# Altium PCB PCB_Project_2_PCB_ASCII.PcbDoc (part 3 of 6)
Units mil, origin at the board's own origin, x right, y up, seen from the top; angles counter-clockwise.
Board outline 3900 x 7800 mil, 6 copper layers (Top Layer, GND 1, Signal, Power, GND 2, Bottom Layer), stack 62.1 mil thick; 636 components, 334 nets, 1830 pads, 1401 vias.
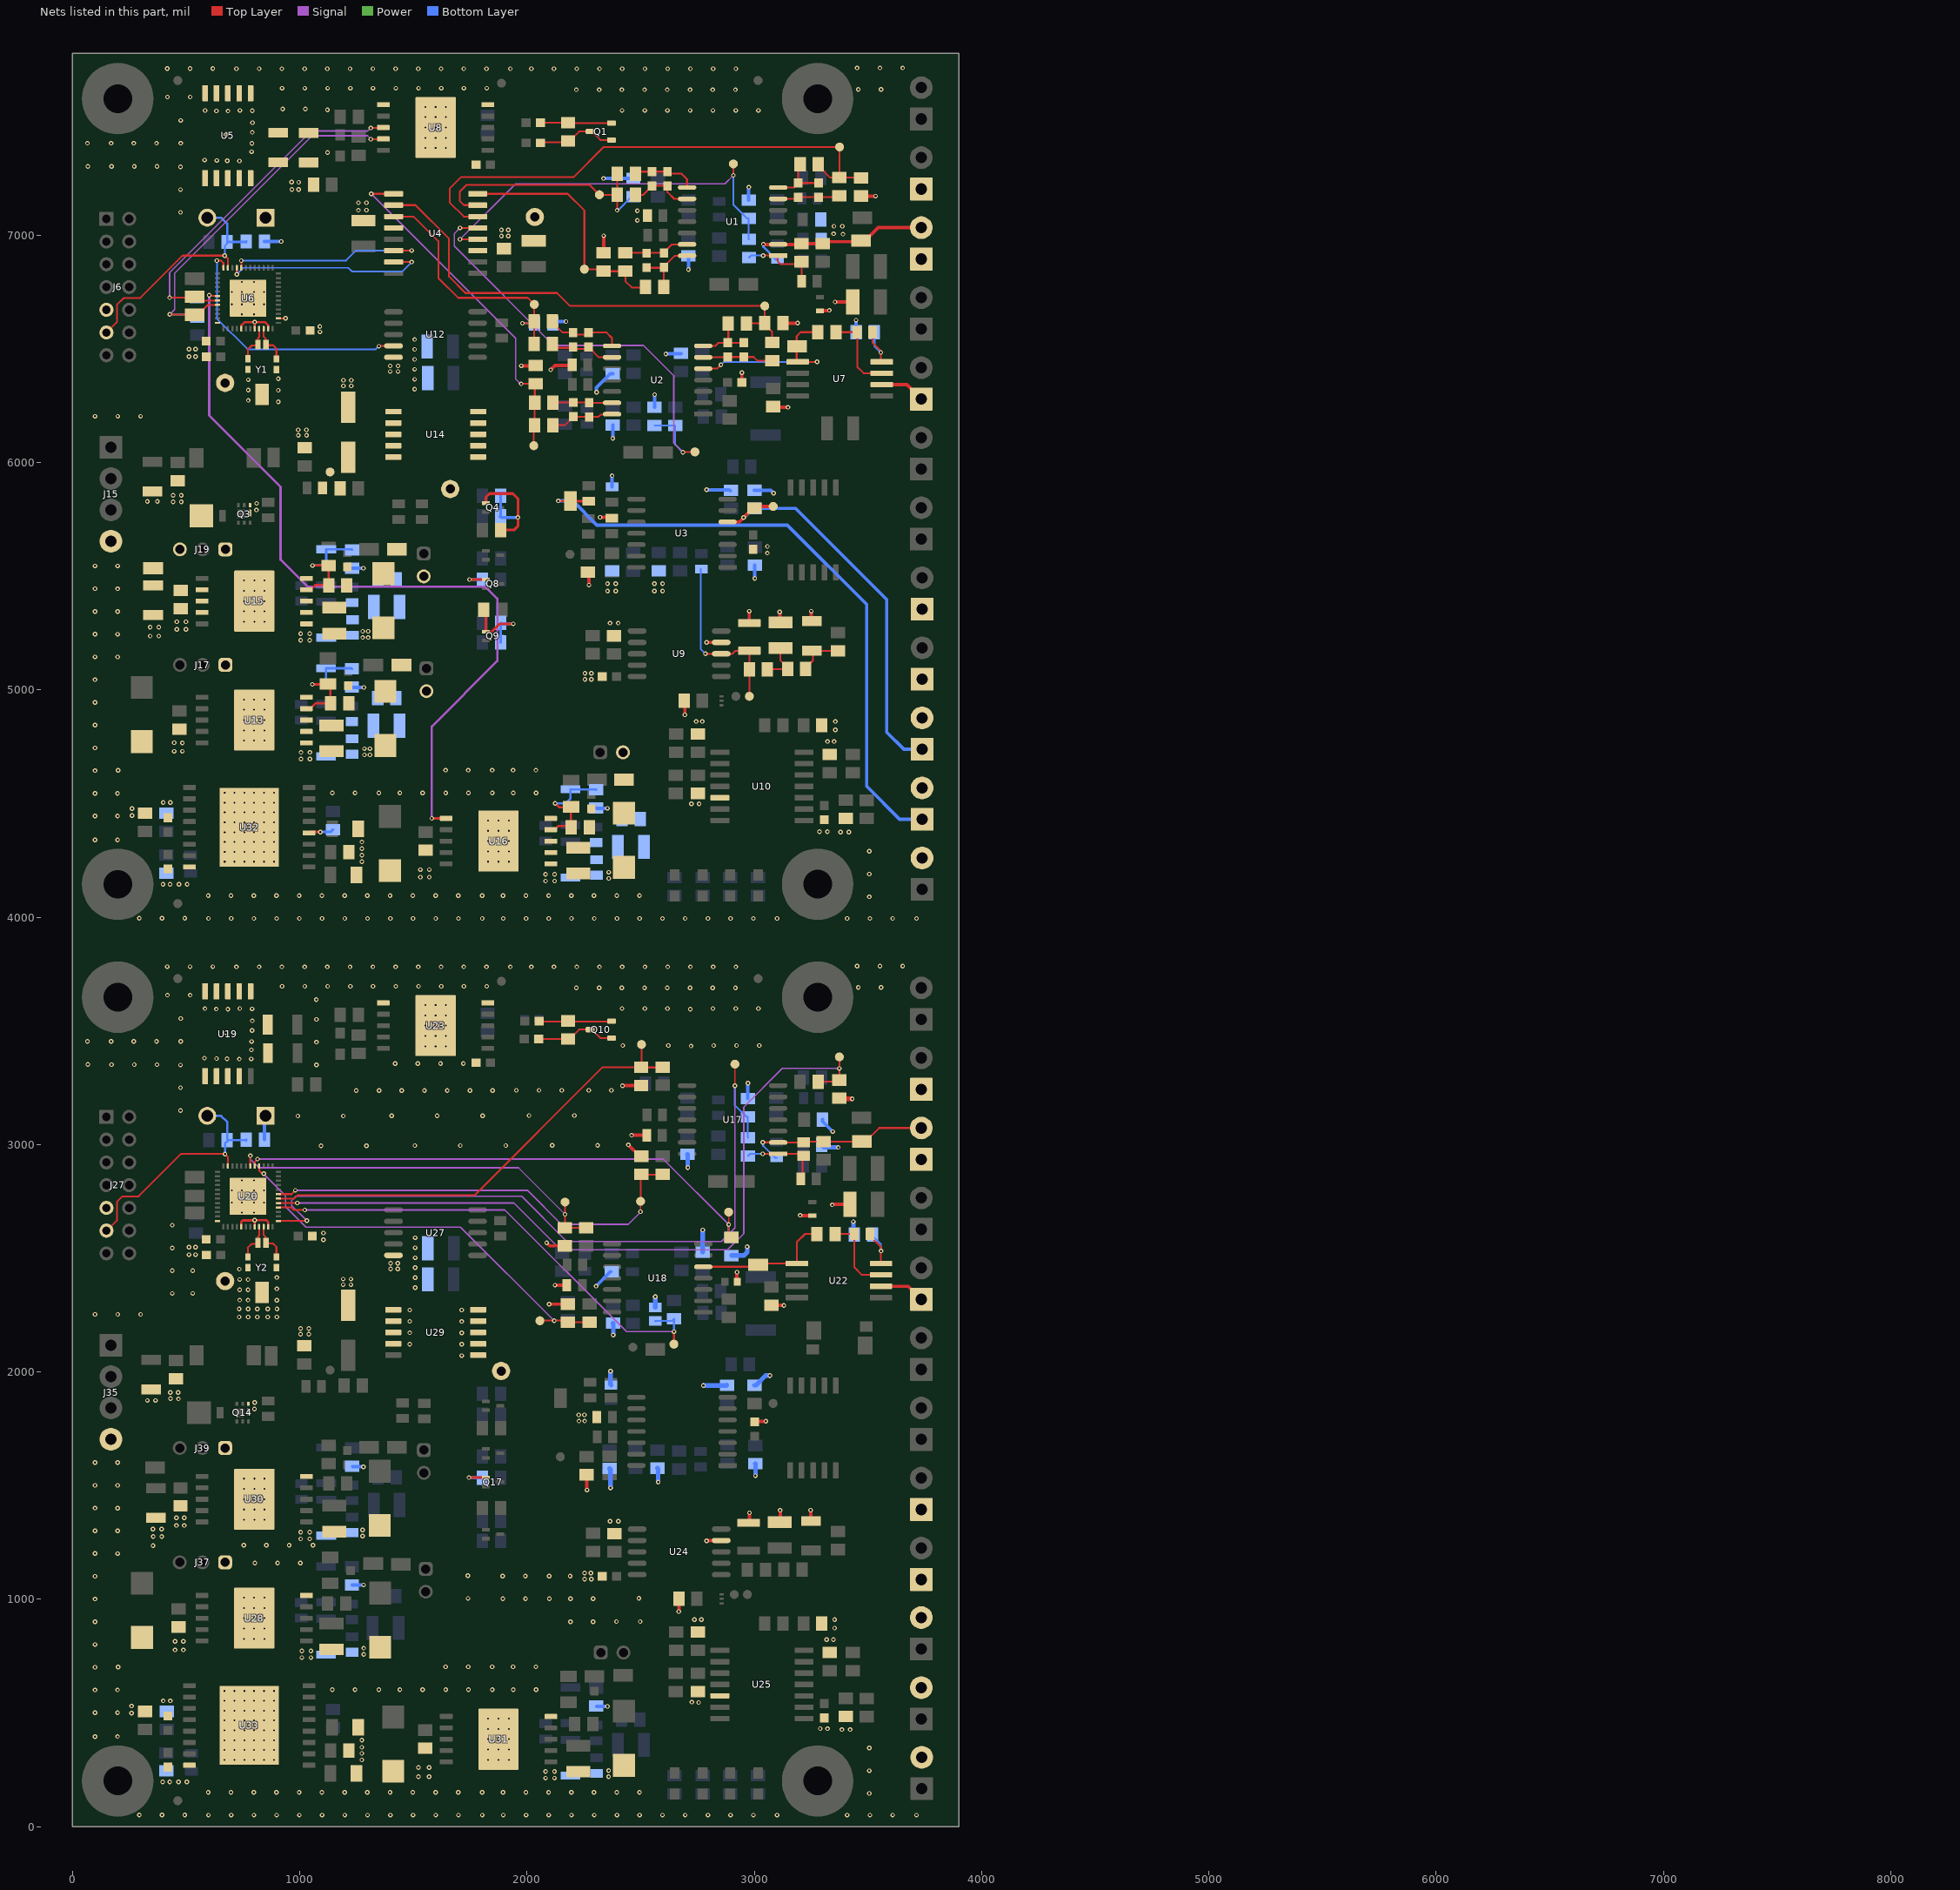
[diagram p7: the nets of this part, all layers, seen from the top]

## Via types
v1: diameter 20, hole 10, Top Layer to Bottom Layer, tented both sides, 1161 vias
v2: diameter 19.68, hole 7.87, Top Layer to Bottom Layer, 240 vias

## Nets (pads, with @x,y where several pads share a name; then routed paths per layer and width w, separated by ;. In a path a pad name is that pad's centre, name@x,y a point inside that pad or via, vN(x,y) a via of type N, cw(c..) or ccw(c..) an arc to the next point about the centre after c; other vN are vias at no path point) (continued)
"Adjustable Voltage Source": J14.1 R105.2 TP26.1 | length 2788.3
  Top Layer w10: v1(2137.7,5831) TP26.1@2191.86,5831 2193.38,5829.48 R105.2@2272,5829.48 R105.2@2276,5829.48
  Bottom Layer w15: v1(2137.7,5831) 2201.67,5831 2307.81,5724.87 3145.86,5724.87 3494.75,5375.97 3494.75,4575.4 3639.7,4430.45 J14.1@3738,4430.45
"Fixed Current Source": J13.1 R97.1 R99.2 TP25.1 U3.5 | length 1817.6
  Top Layer w15: U3.5@2882.73,5738.47 2935.19,5738.47 v1@2957.5,5760.78 ; v1(2953.1,5757.3) 2954.02,5757.3 v1@2957.5,5760.78 ; R97.1@3000.73,5798.47 3008.71,5806.46 3080.53,5806.46 TP25.1@3081.75,5805.23 ; R97.1@3001.42,5800.09 2995.84,5800.09 2957.5,5761.75 v1@2957.5,5760.78
  Bottom Layer w15: v1(2953.1,5757.3) 2953.53,5757.3 2994.23,5798 R99.2@3000.73,5798 3181.45,5798 3582.62,5396.82 3582.62,4813.82 3658,4738.45 J13.1@3738,4738.45
GND: C2.2 C3.1 C4.1 C5.2 C6.2 C7.2 C8.2 C10.2 C12.2 C13.2 C14.2 C15.2 C17.2 C18.2 C19.2 C20.2 C22.2 C23.2 C24.2 C26.2 C27.2 C29.2 C32.2 C33.2 C34.2 C35.2 C36.1 C37.2 C38.2 C39.2 C40.2 C41.2 C42.2 C43.2 C46.2 C47.2 C49.2 C50.2 C52.2 C53.2 C56.2 C57.2 C58.2 C59.2 C64.2 C65.2 C68.2 C69.2 C117.2 C130.2 C131.2 C132.2 D7.1 D10.1 D12.1 J1.1 J3.1 J5.1 J6.9 J7.1 J9.1 J12.2 J13.2 J14.2 J15.4 J17.1 J19.1 Q3.4 Q3.7 Q8.1 R5.2 R8.2 R12.1 R13.1 R15.1 R20.2 R30.1 R37.1 R45.1 R53.1 R70.1 R74.1 R80.1 R85.1 R86.1 R88.1 R89.1 R92.1 R96.1 R98.1 R99.1 R103.1 R104.1 R115.2 R116.1 R122.2 R123.1 R127.1 R130.1 R131.1 R138.2 R139.1 R247.1 R252.1 RT1.1 S1.1 TP4.1 TP16.1 TP30.1 U4.3 U4.12 U5.1 U5.2 U5.3 U5.4 U5.5 U5.6 U5.7 U5.8 U5.9 U6.36 U6.41 U6.44 U6.47 U6.49@773.11,6722.32 U7.2 U8.5 U8.6 U8.11@1598.28,7473.17 U9.4 U10.12 U12.10 U13.10 U13.11@800.07,4866.92 U14.1 U14.2 U14.3 U14.4 U14.5 U14.6 U14.7 U14.8 U14.9 U15.10 U15.11@800.79,5390.09 U16.10 U16.11@1874.92,4334.68 U32.8 U32.17 Y1.3 | length 2686.3
  Top Layer w8: v1(802.16,6617.63) 802.64,6617.63 v1@802.27,6617.27 ; U6.44@802.64,6588.46 U6.44@802.71,6588.54 ; U6.47@861.47,6588.68 U6.47@861.69,6588.46 ; R20.2@2196.46,6426.17 R20.2@2198.97,6428.67 ; C39.2@2268.66,5518.04 C39.2@2272.66,5514.04
  Top Layer w10: U6.41@743.66,6588.54 743.66,6602.61 758.32,6617.27 v1@802.27,6617.27 ; U6.44@802.64,6588.46 802.64,6617.63 846.59,6617.63 861.77,6602.45 U6.47@861.77,6588.54
  Top Layer w12: v1(1747,5485) 1746.28,5485 1745.57,5485.71 Q8.1@1819.44,5485.71 ; C36.1@2978.54,5301.82 C36.1@2978.82,5302.1
  Top Layer w15: v1(1975.09,6424.97) C22.2@2034.09,6424.97 ; v1(2104.59,6407.38) 2123.37,6426.17 R20.2@2196.46,6426.17 ; v1(2272.66,5460.5) C39.2@2272.66,5514.04 ; v1(2321.45,5758.69) 2370.47,5758.69 R8.2@2373.79,5755.37 ; C19.2@2337.62,6932 v1(2337.62,6997) ; R80.1@2691.23,4952.57 2690.66,4952 2694.68,4947.98 v1(2694.68,4889.76) ; v1(2790.17,5208.53) U9.4@2854.71,5208.53 ; C4.1@2945.5,6352 v1(2945.5,6395.22) ; v1(2978.1,5345.65) 2978.1,5302.81 C36.1@2978.82,5302.1 ; C24.2@3086.37,6242.7 3086.48,6242.59 v1(3148.44,6242.59) ; v1(3112.28,5342.73) 3112.28,5300.49 C38.2@3115.56,5297.22 ; C27.2@3126.16,6612.87 v1(3190.98,6612.87) ; v1(3250.54,5345.65) 3250.54,5304.72 C37.2@3253.48,5301.78 ; RT1.1@3289,6667 3290.13,6668.13 3329.47,6668.13 v1(3330.6,6669.26) ; v1(3355.5,6705.9) R37.1@3432.88,6705.9 ; C10.2@3470.01,7171.92 3470.55,7171.38 v1(3534.03,7171.38) ; U7.2@3561.06,6342.56 3670.89,6342.56 J5.1@3735,6278.45
  Bottom Layer w8: S1.1@845.65,7072.39 S1.1@849.72,7076.46 ; R116.1@1230.01,5012.46 R116.1@1232.04,5010.43 ; R96.1@2895.1,5874.98 R96.1@2898.12,5878 ; C29.2@3447.79,6574.13 C29.2@3448.69,6573.23
  Bottom Layer w10: R123.1@1230.72,5535.62 R123.1@1231.66,5534.69 ; R139.1@2304.85,4480.22 R139.1@2305.7,4481.06
  Bottom Layer w12: v1(1747,5485) R130.1@1804.04,5485
  Bottom Layer w15: C20.2@845.65,6971.91 v1(918.93,6971.91) ; R123.1@1231.66,5534.69 v1(1280.38,5534.69) ; R116.1@1232.04,5010.43 v1(1282.88,5010.43) ; C32.2@2114,6612 2121.89,6619.89 2122.05,6619.74 v1(2171.92,6619.74) ; R139.1@2305.7,4481.06 2307.93,4478.82 v1(2354.39,4478.82) ; v1(2306,6309) 2306,6329.68 2367.18,6390.86 R70.1@2377.36,6390.86 ; v1(2337.29,7249.01) 2467.29,7249.01 C15.2@2468.02,7249.74 ; R103.1@2374.52,5892.31 v1(2374.52,5941.99) ; v1(2377.62,6105.75) R53.1@2377.62,6163.62 ; C7.2@2561.53,6243.08 2561.53,6297.99 v1(2561.79,6298.25) ; v1(2611.08,6477.56) 2676.28,6477.56 R15.1@2678,6479.28 ; R45.1@2710.34,6908.48 2710.34,6848.68 v1(2710.68,6848.34) v1@2711.01,6848 ; v1(2790.17,5879.97) 2890.11,5879.97 R96.1@2895.1,5874.98 ; C2.2@2975.86,7153.07 v1(2975.86,7210.55) ; R99.1@3000.73,5878 3072.8,5878 v1(3085.54,5865.26) ; v1(3002.19,5489.56) R12.1@3002.19,5547.72 ; C29.2@3447.79,6574.13 v1(3447.79,6625.95)
  other v1: 598.91,3994.47 698.91,3994.47 798.91,3994.47 898.91,3994.47 998.91,3994.47 1098.91,3994.47 1198.91,3994.47 1298.91,3994.47 1398.91,3994.47 1498.91,3994.47 1598.91,3994.47 1698.91,3994.47 1803.7,3994.47 1896.04,3994.47 1996.04,3994.47 2096.04,3994.47 2196.04,3994.47 2296.04,3994.47 2396.04,3994.47 2496.04,3994.47 2596.04,3994.47 2696.04,3994.47 2796.04,3994.47 2896.04,3994.47 2996.04,3994.47 3100.82,3994.47 3408.93,3994.34 3508.93,3994.34 3608.93,3994.34 3713.72,3994.34 294.77,3994.96 394.77,3994.96 494.77,3994.96 3506.3,4089.76 598.09,4094.63 698.09,4094.63 798.08,4094.63 898.08,4094.63 998.08,4094.63 1098.08,4094.63 1198.08,4094.63 1298.08,4094.63 1398.08,4094.63 1498.08,4094.63 1598.08,4094.63 1698.08,4094.63 1802.87,4094.63 1895.21,4094.63 1995.21,4094.63 2095.21,4094.63 2195.21,4094.63 2295.21,4094.63 2395.21,4094.63 2495.21,4094.63 399.28,4144.49 430.24,4144.49 469.28,4144.49 505,4144.49 2082.01,4158.95 2121.61,4158.95 2359.65,4170.38 1531.44,4176.2 1570.37,4176.2 2082.01,4188.28 2121.61,4188.28 3506.3,4189.76 2359.65,4197.63 1531.44,4209.13 1570.37,4209.13 1274,4244.13 1274,4273.02 3506.3,4289.76 1274,4301.9 1274,4330.79 99.7,4339.87 198.92,4340 3379.74,4373.84 3416,4373.84 3287.19,4375.87 3321.86,4375.87 99.7,4444.66 198.92,4444.79 262.67,4446.7 262.67,4477.66 2757.2,4498.39 2723.49,4498.68 400,4504.02 430.95,4504.02 99.7,4544.66 198.92,4544.79 1143.81,4546.42 1243.81,4546.42 1348.6,4546.42 1440.94,4546.42 1540.94,4546.42 1642.92,4546.42 1742.92,4546.42 1847.71,4546.42 1940.05,4546.42 2040.05,4546.42 99.7,4644.66 201.6,4645.91 1642.09,4646.58 1742.09,4646.58 1846.88,4646.58 1939.22,4646.58 2039.22,4646.58 1006,4695.67 1045.6,4695.67 1285,4713.84 1309.56,4713.84 1006,4725 1045.6,4725 448,4729.5 484.21,4729.5 1285,4741.08 1309.56,4741.08 99.7,4744.66 448,4767.4 484.21,4766.93 3322.42,4772.87 3351.54,4772.87 3357,4823.58 99.7,4844.66 2744.6,4861 2771.23,4861 3357,4861 99.7,4944.66 99.7,5044.66 2255.41,5045.54 2283.03,5045.54 2255.41,5072.63 2283.03,5072.63 199.7,5144.41 99.7,5144.66 1004.67,5217.9 1044.27,5217.9 1277.32,5230.23 1301.89,5230.23 342.6,5236.11 380.37,5236.11 199.7,5244.41 99.7,5244.66 1004.67,5247.24 1044.27,5247.24 1277.32,5257.48 1301.89,5257.48 460,5266.05 500.27,5266.05 342.41,5275.31 380.37,5275.31 2365.27,5293.28 2401.54,5293.28 460,5299.54 500.27,5299.54 199.7,5344.41 99.7,5344.66 2354.69,5434.63 2390.22,5434.63 2561,5434.63 2596.53,5434.63 199.7,5444.41 99.7,5444.66 2354.69,5466.58 2390.22,5466.58 2561,5466.58 2596.53,5466.58 99.7,5544.66 199.83,5544.66 3057.91,5601.47 3057.91,5630.46 810,5791 811,5820 443.37,5826.73 479.54,5826.73 330.24,5828.44 374.3,5828.44 443.37,5855.73 479.54,5855.73 994.29,6119 1030.71,6119 994,6143.5 1030.42,6143.5 100,6203.06 200.24,6202.93 300.24,6202.93 906.29,6266.75 774.06,6273.09 906.29,6317.42 774.06,6318.37 1505.97,6321.83 1192.54,6336.7 1226.91,6336.7 1192.54,6361.37 1226.91,6361.37 774.06,6363.65 1505.97,6365.67 906.29,6368.1 1398.25,6400.12 1432.62,6400.12 1505.97,6409.51 1398.25,6424.8 1432.62,6424.8 1505.97,6453.35 513.02,6465.59 541.89,6465.59 1505.97,6497.19 513.02,6498.54 541.89,6498.54 1505.97,6541.03 1089.08,6574.1 1088.63,6597.94 1888,6995.38 1917.72,6995.38 3390.56,7003.98 3349.06,7005.89 1888,7022.79 1917.72,7022.79 3350.67,7038.98 3387.9,7039.01 2485.65,7065.04 476.18,7099.94 2485.65,7106.35 1258.63,7109.19 1294.46,7109.49 1258.63,7142 1294.46,7142.3 476.18,7199.94 476.18,7299.94 68.54,7302.08 172.69,7301.58 272.69,7301.58 372.69,7301.58 735.72,7325.78 681.81,7327.19 635.4,7328.13 581.95,7330 1122.84,7363.32 788.69,7366.57 789.84,7403.15 66.42,7404.09 170.56,7404.09 270.56,7404.09 370.56,7404.09 476.68,7404.09 675.71,7441.58 791.82,7451.75 792.81,7494.41 476.68,7504.09 685.05,7545.42 634.1,7545.99 791.98,7546.59 584.5,7547.97 737.35,7548.25 2418.34,7548.18 2518.34,7548.18 2618.34,7548.18 2718.33,7548.18 2818.34,7548.18 2918.34,7548.18 3018.33,7548.18 1122.4,7550.35 925.24,7554.12 1025.24,7554.12 418.47,7607.12 518.47,7607.12 2217.41,7639.22 2317.41,7639.22 2417.41,7639.22 2517.41,7639.22 2617.41,7639.22 2717.41,7639.22 2817.41,7639.22 2917.41,7639.22 3457.81,7640.91 3557.81,7640.91 923.08,7645.8 1023.08,7645.8 1123.08,7645.8 1223.08,7645.8 1323.08,7645.8 1423.08,7645.8 1523.08,7645.8 1623.08,7645.8 1723.08,7645.8 1823.08,7645.8 417.95,7732.24 517.95,7732.24 617.95,7732.24 722.1,7731.74 822.1,7731.74 922.1,7731.74 1022.1,7731.74 1122.1,7731.74 1222.1,7731.74 1322.1,7731.74 1422.1,7731.74 1522.1,7731.74 1622.1,7731.74 1722.1,7731.74 1822.1,7731.74 1926.88,7731.74 2019.22,7731.74 2119.22,7731.74 2219.22,7731.74 2319.22,7731.74 2419.22,7731.74 2519.22,7731.74 2619.22,7731.74 2719.22,7731.74 2819.22,7731.74 2919.22,7731.74 3452.89,7735.08 3552.89,7735.08 3652.89,7735.08
  other v2: 670.35,4244.17 713.66,4244.17 756.97,4244.17 800.27,4244.17 843.58,4244.17 886.89,4244.17 1829.64,4244.13 1874.92,4244.13 1920.19,4244.13 670.35,4287.48 713.66,4287.48 756.97,4287.48 800.27,4287.48 843.58,4287.48 886.89,4287.48 1829.64,4289.41 1874.92,4289.41 1920.19,4289.41 670.35,4330.79 713.66,4330.79 756.97,4330.79 800.27,4330.79 843.58,4330.79 886.89,4330.79 1829.64,4334.68 1874.92,4334.68 1920.19,4334.68 670.35,4374.1 713.66,4374.1 756.97,4374.1 800.27,4374.1 843.58,4374.1 886.89,4374.1 1829.64,4379.96 1874.92,4379.96 1920.19,4379.96 670.35,4417.4 713.66,4417.4 756.97,4417.4 800.27,4417.4 843.58,4417.4 886.89,4417.4 1829.64,4425.23 1874.92,4425.23 1920.19,4425.23 670.35,4460.71 713.66,4460.71 756.97,4460.71 800.27,4460.71 843.58,4460.71 886.89,4460.71 670.35,4504.02 713.66,4504.02 756.97,4504.02 800.27,4504.02 843.58,4504.02 886.89,4504.02 670.35,4547.32 713.66,4547.32 756.97,4547.32 800.27,4547.32 843.58,4547.32 886.89,4547.32 754.8,4776.37 800.07,4776.37 845.35,4776.37 754.8,4821.65 800.07,4821.65 845.35,4821.65 754.8,4866.92 800.07,4866.92 845.35,4866.92 754.8,4912.2 800.07,4912.2 845.35,4912.2 754.8,4957.48 800.07,4957.48 845.35,4957.48 755.51,5299.54 800.79,5299.54 846.06,5299.54 755.51,5344.81 800.79,5344.81 846.06,5344.81 755.51,5390.09 800.79,5390.09 846.06,5390.09 755.51,5435.36 800.79,5435.36 846.06,5435.36 755.51,5480.64 800.79,5480.64 846.06,5480.64 746.14,6651.45 800.08,6651.45 702.24,6695.35 746.14,6695.35 800.08,6695.35 843.97,6695.35 702.24,6749.29 746.14,6749.29 800.08,6749.29 843.97,6749.29 746.14,6793.18 800.08,6793.18 1553,7382.62 1598.28,7382.62 1643.55,7382.62 1553,7427.89 1598.28,7427.89 1643.55,7427.89 1553,7473.17 1598.28,7473.17 1643.55,7473.17 1553,7518.44 1598.28,7518.44 1643.55,7518.44 1553,7563.72 1598.28,7563.72 1643.55,7563.72
GND(m): C71.2 C72.1 C73.2 C74.2 C75.2 C76.2 C77.2 C78.2 C79.2 C80.2 C81.2 C82.1 C83.2 C84.2 C85.2 C86.2 C87.2 C88.2 C90.2 C92.2 C93.2 C94.2 C95.1 C96.2 C97.2 C98.2 C99.2 C100.2 C101.2 C102.2 C103.2 C105.2 C106.2 C109.2 C110.2 C112.2 C113.2 C118.2 C119.2 C120.2 C121.2 C124.2 C125.2 C128.2 C129.2 C134.2 C135.2 C136.2 C137.2 D19.1 D22.1 D24.1 J21.1 J23.1 J26.1 J27.9 J28.1 J30.1 J32.2 J33.2 J34.2 J35.4 J37.1 J39.1 Q14.4 Q14.7 Q17.1 R144.2 R149.1 R150.1 R152.1 R158.2 R164.1 R169.1 R174.2 R178.1 R184.1 R198.1 R201.1 R205.1 R211.1 R212.1 R215.1 R216.1 R219.1 R221.1 R224.1 R226.1 R228.1 R233.1 R242.2 R243.1 R251.2 R254.1 R257.1 R265.2 R266.1 R267.1 R268.1 R269.1 R270.1 RT2.1 S2.1 TP51.1 TP64.1 U19.1 U19.2 U19.3 U19.4 U19.5 U19.6 U19.7 U19.8 U19.9 U20.36 U20.41 U20.44 U20.47 U20.49@773.11,2772.32 U22.2 U23.5 U23.6 U23.11@1598.28,3523.17 U24.4 U25.12 U27.10 U28.10 U28.11@800.07,916.93 U29.1 U29.2 U29.3 U29.4 U29.5 U29.6 U29.7 U29.8 U29.9 U30.10 U30.11@800.79,1440.09 U31.10 U31.11@1874.98,384.68 U33.8 U33.17 Y2.3 | length 3057.3
  Top Layer w8: v1@802.16,2666.63 802.64,2666.63 v1@802.27,2666.27 ; U20.44@802.64,2637.46 U20.44@802.71,2637.54 ; U20.47@861.47,2637.68 U20.47@861.69,2637.46 ; R205.1@2667.27,1001 R205.1@2668.15,1001.88
  Top Layer w10: U20.41@743.66,2637.54 743.66,2660.11 749.82,2666.27 v1@802.27,2666.27 ; U20.44@802.64,2637.46 802.64,2666.63 854.6,2666.63 861.77,2659.46 U20.47@861.77,2637.54
  Top Layer w12: v1@1744.86,1536.17 Q17.1@1820.43,1536.17 ; TP64.1@1895.55,2003.98 TP64.1@1905.17,1994.37 ; C95.1@2978.9,1351.99 C95.1@2979.18,1352.27
  Top Layer w15: v1(2086.76,2568) 2100.33,2554.44 C93.2@2166.47,2554.44 ; v1(2098,2298) C84.2@2180,2298 ; v1@2123,2382 v1(2123.3,2381.7) 2123.61,2381.39 R158.2@2175.46,2381.39 ; C99.2@2262.66,1548.04 2262.66,1482.03 v1(2264.37,1480.32) ; v1(2420.3,3259) 2420.59,3259.29 C78.2@2502.51,3259.29 ; v1(2445.85,2999) 2496.31,2948.54 C81.2@2502.81,2948.54 ; v1(2460.5,3041) R144.2@2527.35,3041 ; R205.1@2667.27,1001 2668.15,1000.12 v1(2668.15,946.09) ; v1(2790.84,1257.51) 2851.51,1257.51 2853.9,1259.89 U24.4@2855.08,1258.71 ; v1(2924.23,2438.85) 2924.23,2398.56 C72.1@2925.82,2396.98 ; v1(2979.12,1380.69) 2979.12,1352.34 C95.1@2979.18,1352.27 ; C82.1@3002.19,1780.6 3004.72,1783.13 v1(3051.15,1783.13) ; C87.2@3075.12,2292.86 3129.65,2292.86 v1(3130.43,2292.08) ; C97.2@3114.22,1354.96 v1(3114.22,1391.51) ; v1(3201.77,2689.1) 3203.87,2687 RT2.1@3255.41,2687 ; C96.2@3248.07,1364.58 v1(3248.07,1392.12) ; v1(3343,2735) 3345,2737 R169.1@3420.98,2737 ; U22.2@3557.76,2376.37 U22.2@3557.51,2376.63 3677.47,2376.63 J26.1@3735,2319.1
  Top Layer w20: C74.2@3374.38,3203.55 3377.09,3200.84 v1(3430.95,3200.84)
  Bottom Layer w8: S2.1@845.65,3122.39 S2.1@849.72,3126.46 ; v1@2304,2377 v1(2304.19,2377) v1@2304.37,2377 ; R198.1@2367.31,2439.93 R198.1@2373.81,2439.93
  Bottom Layer w10: R254.1@1230.72,1585.62 R254.1@1233.66,1582.69 ; R266.1@2304.5,529.89 2305.35,530.74 R266.1@2307.58,528.5
  Bottom Layer w12: v1@1744.51,1534.68 R257.1@1803.69,1534.68
  Bottom Layer w15: C83.2@845.65,3021.91 S2.1@845.65,3122.39 ; R243.1@1230.94,1063.15 v1(1281.78,1063.15) ; R254.1@1233.66,1582.69 v1(1280.38,1582.69) ; v1@2304.37,2377 R198.1@2367.31,2439.93 ; R266.1@2307.58,528.5 v1@2354.04,528.5 ; C71.2@2971.92,3202.09 v1(2971.92,3269.74) ; R164.1@3301,3110 3301,3101.74 v1(3345.46,3057.28)
  Bottom Layer w20: R211.1@2363.79,1575.09 2367.52,1571.37 v1(2367.52,1490.03) ; v1(2367.91,2003.6) 2367.91,1944.56 R228.1@2370,1942.46 ; R184.1@2378.87,2214.07 2379.73,2213.21 v1(2379.73,2162.53) ; C73.2@2564,2283.53 2564.88,2284.41 v1(2564.88,2330.52) ; R212.1@2574.22,1576.61 2577.32,1573.51 v1(2577.32,1515.4) ; R178.1@2706.4,2957.5 2707.46,2956.44 v1(2707.46,2898.48) ; R152.1@2773,2527 v1(2773,2624.49) ; v1(2776.21,1939.81) 2877.78,1939.81 R221.1@2879.81,1941.84 ; C88.2@2900.17,2512.01 2953.8,2512.01 2969.07,2527.28 v1(2969.07,2550.86) ; R224.1@3000.72,1941 3007.22,1941 3050.33,1984.11 v1(3069.03,1984.11) ; R150.1@3004.67,1596.24 3005.45,1595.47 v1(3005.45,1543.39) ; R149.1@3296.1,2998.64 3307.21,2987.53 v1(3369.65,2987.53) ; v1(3435.98,2660.91) 3435.98,2609.02 C90.2@3440,2605
  other v1: 294.77,51.49 394.77,51.49 494.77,51.49 598.91,51 698.91,51 798.91,51 898.91,51 998.91,51 1098.91,51 1198.91,51 1298.91,51 1398.91,51 1498.91,51 1598.91,51 1698.91,51 1803.7,51 1896.04,51 1996.04,51 2096.04,51 2196.04,51 2296.04,51 2396.04,51 2496.04,51 2596.04,51 2696.04,51 2796.04,51 2896.04,51 2996.04,51 3100.82,51 3408.93,50.87 3508.93,50.87 3608.93,50.87 3713.72,50.87 3506.3,146.29 598.09,151.16 698.09,151.16 798.08,151.16 898.08,151.16 998.08,151.16 1098.08,151.16 1198.08,151.16 1298.08,151.16 1398.08,151.16 1498.08,151.16 1598.08,151.16 1698.08,151.16 1802.87,151.16 1895.21,151.16 1995.21,151.16 2095.21,151.16 2195.21,151.16 2295.21,151.16 2395.21,151.16 2495.21,151.16 397.77,197.17 428.72,197.17 467.77,197.17 503.49,197.17 2081.75,213.49 2121.36,213.49 1522.86,219.93 1569.86,219.93 2359.39,219.93 2081.75,242.82 2121.36,242.82 3506.3,246.29 2359.39,247.17 1522.86,260.19 1569.86,260.19 1273.74,293.68 1273.74,322.29 3506.3,346.29 1273.74,348.96 1273.74,380.33 99.7,396.4 198.92,396.53 3385.53,427.35 3421.79,427.35 3290.53,431.25 3322.29,431.1 260.9,499.52 99.7,501.19 198.92,501.32 2354.45,528.82 260.9,530.47 2755.31,546.39 2725.5,547.87 399.75,553.56 430.7,553.56 99.7,601.19 198.92,601.32 1143.81,602.95 1243.81,602.95 1348.6,602.95 1440.94,602.95 1540.94,602.95 1642.92,602.95 1742.92,602.95 1847.71,602.95 1940.05,602.95 2040.05,602.95 99.7,701.19 201.6,702.44 1642.09,703.11 1742.09,703.11 1846.88,703.11 1939.22,703.11 2039.22,703.11 1010,743.67 1049.6,743.67 1282,757.84 1010,773 1049.6,773 452,777.5 488.21,777.5 1282,785.08 99.7,801.19 452,815.4 488.21,814.93 3319.02,822.66 3348.15,822.66 3353.61,873.36 99.7,901.19 2191.51,901.2 2291.1,901.2 2393.9,902.27 2498.16,902.27 2737,910.6 2767.84,910.79 3353.61,910.79 99.7,1001.19 1893.97,1002.25 1993.97,1002.25 2098.76,1002.25 2191.1,1002.25 2291.1,1002.25 1740.95,1003.77 2492.67,1004.65 2253.73,1088.67 2283.35,1088.67 99.7,1101.19 1893.14,1102.41 1993.14,1102.41 2097.93,1102.41 2190.27,1102.41 1740.12,1103.93 2253.73,1115.76 2281.35,1115.76 803.09,1159.69 903.09,1159.69 1003.09,1159.69 99.7,1201.19 199.7,1200.94 355.06,1236.43 754.08,1237.86 854.08,1237.86 954.08,1237.86 1058.87,1237.86 1004.67,1265.9 1044.27,1265.9 355.73,1275.83 393.37,1275.83 1276.67,1277.81 1004.67,1295.24 1044.27,1295.24 99.7,1301.19 199.7,1300.94 1276.67,1305.05 354.74,1309.17 392.96,1309.17 458,1324.76 492.67,1324.76 2365.64,1343.45 2401.9,1343.45 458,1358.24 492.67,1358.24 99.7,1401.19 199.7,1400.94 99.7,1501.18 199.7,1500.94 1744.86,1535 99.7,1601.18 199.83,1601.18 2229,1783.81 2254,1783.81 2228,1811.18 2253,1811.18 801.13,1836.91 802.13,1865.91 330.2,1874.48 365.85,1874.48 466.71,1881.43 432.07,1882.47 465.33,1909.49 430.68,1909.84 1712.76,2071.58 1484.43,2122.32 1712.76,2121.78 1004.29,2166 1040.71,2166 1484.43,2172.34 1712.76,2171.97 1004,2190.5 1040.42,2190.5 1484.43,2222.35 1712.76,2222.17 733.85,2241.58 773.67,2241.58 814.02,2241.58 859.92,2241.58 900.27,2241.58 100,2253.06 200.24,2252.93 300.24,2252.93 1484.43,2272.36 1712.76,2272.36 733.91,2277.28 773.73,2277.28 814.08,2277.28 859.98,2277.28 900.33,2277.28 900.3,2315.14 736.22,2316 773.14,2315.75 439.47,2345.26 529.5,2345.26 736.22,2361.28 773.14,2361.03 899.52,2365.61 1508.17,2370.42 1191.54,2383.7 1225.91,2383.7 773.14,2406.31 736.22,2406.56 1191.54,2408.37 1225.91,2408.37 1508.17,2414.39 899.91,2415.31 439.47,2445.26 529.5,2445.26 734.81,2452.21 1400.14,2452.81 1431.85,2452.81 1508.17,2458.37 1400.33,2478.25 1431.85,2478.25 1508.17,2502.34 513.02,2515.59 541.89,2515.59 439.47,2545.26 1508.17,2546.31 513.02,2548.54 541.89,2548.54 1104.87,2581.63 1508.17,2590.28 1104.87,2610.97 439.47,2645.26 802.6,2667.78 1093.98,2994.86 1293.98,2994.86 1506.92,2995.71 1706.92,2995.71 1906.92,2995.71 2110.89,2996.91 2310.89,2996.91 992.21,3125.5 1192.21,3125.5 1405.15,3126.35 1605.15,3126.35 1805.15,3126.35 2009.12,3127.55 2209.12,3127.55 476.18,3149.94 1249.25,3237.49 1349.25,3237.49 1449.25,3237.49 1549.25,3237.49 1649.25,3237.49 1749.25,3237.49 1849.25,3237.49 1953.23,3238.68 2053.23,3238.68 2153.23,3238.68 2271.78,3238.59 2371.78,3238.59 476.18,3249.94 476.18,3349.94 1073.74,3350.54 68.54,3352.08 172.69,3351.58 272.69,3351.58 372.69,3351.58 1420.1,3356.46 1520.1,3356.46 1620.1,3356.46 1720.1,3356.46 734.88,3375.87 680.97,3377.28 786.92,3376.81 634.56,3378.22 581.12,3380.09 787.86,3416.66 2722.14,3433.31 2421.76,3435.7 2621.76,3435.7 2821.76,3435.7 2921.76,3435.7 3021.76,3435.7 1073.74,3450.54 789,3453.24 66.42,3454.09 170.56,3454.09 270.56,3454.09 370.56,3454.09 476.68,3454.09 674.88,3491.67 790.98,3501.84 791.98,3544.5 1073.74,3550.54 476.68,3554.09 633.26,3596.08 684.22,3595.51 2718.72,3595.8 791.14,3596.68 583.67,3598.06 736.52,3598.34 2418.34,3598.18 2518.34,3598.18 2618.34,3598.18 2818.34,3598.18 2918.34,3598.18 3018.33,3598.18 1073.3,3637.58 418.47,3657.12 518.47,3657.12 2217.41,3689.22 2317.41,3689.22 2417.41,3689.22 2517.41,3689.22 2617.41,3689.22 2717.41,3689.22 2817.41,3689.22 2917.41,3689.22 3457.81,3690.91 3557.81,3690.91 923.08,3695.8 1023.08,3695.8 1123.08,3695.8 1223.08,3695.8 1323.08,3695.8 1423.08,3695.8 1523.08,3695.8 1623.08,3695.8 1723.08,3695.8 1823.08,3695.8 417.95,3782.24 517.95,3782.24 617.95,3782.24 722.1,3781.74 822.1,3781.74 922.1,3781.74 1022.1,3781.74 1122.1,3781.74 1222.1,3781.74 1322.1,3781.74 1422.1,3781.74 1522.1,3781.74 1622.1,3781.74 1722.1,3781.74 1822.1,3781.74 1926.89,3781.74 2019.22,3781.74 2119.22,3781.74 2219.22,3781.74 2319.22,3781.74 2419.22,3781.74 2519.22,3781.74 2619.22,3781.74 2719.22,3781.74 2819.22,3781.74 2919.22,3781.74 3452.89,3785.08 3552.89,3785.08 3652.89,3785.08
  other v2: 670.1,293.72 713.4,293.72 756.71,293.72 800.02,293.72 843.33,293.72 886.63,293.72 1829.7,294.13 1874.98,294.13 1920.25,294.13 670.1,337.03 713.4,337.03 756.71,337.03 800.02,337.03 843.33,337.03 886.63,337.03 1829.7,339.41 1874.98,339.41 1920.25,339.41 670.1,380.33 713.4,380.33 756.71,380.33 800.02,380.33 843.33,380.33 886.63,380.33 1829.7,384.68 1874.98,384.68 1920.25,384.68 670.1,423.64 713.4,423.64 756.71,423.64 800.02,423.64 843.33,423.64 886.63,423.64 1829.7,429.96 1874.98,429.96 1920.25,429.96 670.1,466.95 713.4,466.95 756.71,466.95 800.02,466.95 843.33,466.95 886.63,466.95 1829.7,475.23 1874.98,475.23 1920.25,475.23 670.1,510.26 713.4,510.26 756.71,510.26 800.02,510.26 843.33,510.26 886.63,510.26 670.1,553.56 713.4,553.56 756.71,553.56 800.02,553.56 843.33,553.56 886.63,553.56 670.1,596.87 713.4,596.87 756.71,596.87 800.02,596.87 843.33,596.87 886.63,596.87 754.8,826.37 800.07,826.37 845.35,826.37 754.8,871.65 800.07,871.65 845.35,871.65 754.8,916.93 800.07,916.93 845.35,916.93 754.8,962.2 800.07,962.2 845.35,962.2 754.8,1007.48 800.07,1007.48 845.35,1007.48 755.51,1349.54 800.79,1349.54 846.06,1349.54 755.51,1394.81 800.79,1394.81 846.06,1394.81 755.51,1440.09 800.79,1440.09 846.06,1440.09 755.51,1485.36 800.79,1485.36 846.06,1485.36 755.51,1530.64 800.79,1530.64 846.06,1530.64 746.14,2701.45 800.08,2701.45 702.24,2745.35 746.14,2745.35 800.08,2745.35 843.97,2745.35 702.24,2799.29 746.14,2799.29 800.08,2799.29 843.97,2799.29 746.14,2843.18 800.08,2843.18 1553,3432.62 1598.28,3432.62 1643.55,3432.62 1553,3477.89 1598.28,3477.89 1643.55,3477.89 1553,3523.17 1598.28,3523.17 1643.55,3523.17 1553,3568.44 1598.28,3568.44 1643.55,3568.44 1553,3613.72 1598.28,3613.72 1643.55,3613.72
"I2C SCL": R41.1 TP10.1 U6.32 U8.9 | length 1739
  Top Layer w8: v1(428.55,6650.98) 544.66,6650.98 549.63,6646 596.63,6693 639.04,6693 U6.32@639.25,6692.79 ; v1(1313.58,7421.72) 1313.72,7421.86 1368.94,7421.86 U8.9@1369.08,7422
  Signal w6.5: v1(428.55,6650.98) 450.06,6672.48 450.06,6832.03 1054.75,7436.72 1298.59,7436.72 v1@1312.33,7422.98 ; v1(1313.58,7421.72) v1@1312.33,7422.98 ; v1@1314.16,7422.98 v1@1312.33,7422.98
  Bottom Layer w8: v1(428.55,6650.98) 546.01,6650.98 549.58,6647.4 554.09,6651.91 R41.1@560,6646 ; R41.1@557.18,6646 R41.1@558.45,6644.73
"I2C SDA": R39.1 TP9.1 U6.31 U8.8 | length 1667.2
  Top Layer w8: v1(428.4,6724.73) 541.6,6724.73 542.95,6726.07 544.57,6724.45 TP9.1@548.75,6728.63 ; TP9.1@546.66,6725.69 560.35,6712 636,6712 U6.31@635.53,6712.47 ; v1(1313.58,7471.01) 1314.08,7471.5 1368.58,7471.5 U8.8@1369.08,7472
  Signal w6.5: v1(428.4,6724.73) 428.4,6835.02 1051.44,7458.07 1299.97,7458.07 v1@1314.16,7472.26
  Bottom Layer w8: v1(428.4,6724.73) 551.48,6724.73 552.83,6726.07 554.45,6724.45 R39.1@558,6728
"LDO Enable": U6.30 U16.1 | length 3504.8
  Top Layer w8: v1(602.33,6735.65) 605.58,6735.65 609.07,6732.16 U6.30@639.25,6732.16 U6.30@639.44,6732.35
  Top Layer w12: v1(1581.76,4434.68) U16.1@1645,4434.68
  Signal w10: v1(602.33,6735.65) 602.33,6206.56 916.33,5892.56 916.33,5572.5 1034.86,5453.96 1816.42,5453.96 1869.63,5400.76 1869.63,5126.86 1581.76,4838.99 v1(1581.76,4434.68)
MISO_4wire: U4.15 U6.21 | length 913
  Top Layer w8: U6.21@723.9,6856.18 724.01,6856.06 724.01,6827.46 v1(724.13,6827.34) ; U4.15@1414.04,6881.98 v1@1493.56,6881.98
  Bottom Layer w7.5: v1(724.13,6827.34) 752.97,6856.18 1214.25,6856.18 1229.92,6840.5 1452.08,6840.5 v1(1493.22,6881.64)
MOSI_3wire: U6.24 U12.9 | length 1148.4
  Top Layer w8: v1(636,6887.79) 654.26,6887.79 664.61,6877.44 664.61,6856.41 U6.24@664.84,6856.18 ; v1(1348.77,6511.18) 1349.44,6511.85 1412.33,6511.85 U12.9@1413,6512.51
  Bottom Layer w7.5: v1(636,6887.79) 636,6633 771.5,6497.5 1335.09,6497.5 v1(1348.77,6511.18)
MOSI_4wire: U4.14 U6.20 | length 878.7
  Top Layer w8: U6.20@743.58,6856.18 v1(743.58,6887.79) ; U4.14@1414.27,6932.21 v1@1493.33,6932.21
  Bottom Layer w7.5: v1(743.58,6887.79) 1204.33,6887.79 1248.64,6932.1 v1(1493.22,6932.1)
NetC1_1: C1.1 R2.1 R10.1 U1.1 | length 361.3
  Top Layer w8: v1(3039,6910) 3102.75,6910 3103.75,6911 U1.1@3105.56,6909.19 3102.56,6906.19 3102.56,6885.15 3116.06,6871.65 3196.76,6871.65 C1.1@3208.09,6882.98 3208.09,6797.62 R2.1@3208.54,6797.17
  Bottom Layer w8: R10.1@2977.02,6901.08 2986.94,6911 2987.94,6910 v1(3039,6910)
NetC1_2: C1.2 J1.2 R1.1 R6.1 TP1.1 U1.2 | length 827.1
  Top Layer w15: v1@3045.41,6959.03 v1@3045.31,6959.13 ; R1.1@3302,6963 C1.2@3208.09,6962.98 3204.3,6959.19 U1.2@3105.56,6959.19 3063.57,6959.19 3063.51,6959.13 v1@3045.31,6959.13 ; R1.1@3311.98,6962.98 3319.91,6970.91 3469.61,6970.91 TP1.1@3477.5,6963.02 ; TP1.1@3470.28,6975.71 3488.46,6975.71 3545.19,7032.45 J1.2@3735,7032.45 ; v1@3045.31,6959.13 3044.44,6960 v1(3040,6960) 3040.87,6959.13 v1@3045.31,6959.13
  Bottom Layer w10: v1(3040,6960) 3040,6948.1 3094.49,6893.61 R6.1@3102.56,6893.61
NetC2_1: C2.1 R10.2 TP2.1 U4.4 | length 1761.1
  Top Layer w8: v1(1705.89,6981.57) U4.4@1783.7,6981.57 ; v1(2908.22,7262.85) TP2.1@2908.22,7313
  Signal w6.5: v1(1705.89,6981.57) 1950.29,7225.96 2871.34,7225.96 v1(2908.22,7262.85)
  Bottom Layer w8: v1(2908.22,7262.85) 2908.22,7133.78 2968.93,7073.07 C2.1@2975.86,7073.07 2975.86,6982.24 R10.2@2977.02,6981.08
NetC7_1: C7.1 R17.2 TP3.1 U4.5 | length 2000.1
  Top Layer w8: v1(1705.28,7031.57) U4.5@1783.7,7031.57 ; v1(2686.35,6045.03) 2737.6,6045.03 TP3.1@2739.13,6046.56
  Signal w6.5: v1(1705.28,7031.57) 1680.14,7006.43 1680.14,6951.37 2116.86,6514.66 2512.96,6514.66 2645.86,6381.76 2645.86,6085.52 v1(2686.35,6045.03)
  Bottom Layer w8: C7.1@2561.53,6163.08 2562.09,6162.53 R17.2@2652.11,6162.53 2652.11,6079.27 v1(2686.35,6045.03)
NetC9_1: C9.1 R25.2 R28.1 U1.7 | length 272.2
  Top Layer w8: U1.7@3105.56,7209.19 3174.51,7209.19 3193.74,7228.42 R25.2@3193.74,7229.4 ; R28.1@3201.9,7311.35 3193.74,7303.18 R25.2@3193.74,7229.4 ; C9.1@3283.46,7229.4 R25.2@3193.74,7229.4
NetC9_2: C9.2 R21.1 R25.1 U1.6 | length 277.8
  Top Layer w8: U1.6@3105.56,7159.19 3186.52,7159.19 R25.1@3193.74,7166.41 C9.2@3283.46,7166.41 3369.55,7166.41 R21.1@3377.23,7158.72
NetC10_1: C10.1 R21.2 R28.2 TP6.1 U4.6 | length 2379.1
  Top Layer w8: U4.6@1783.7,7081.57 1722.15,7081.57 1660,7143.72 1660,7205 1710.83,7255.83 2206.44,7255.83 2338.02,7387.4 TP6.1@3375.38,7387.4 3375.38,7252.68 3375.38,7240.58 3377.23,7238.72 3392.17,7253.67 3454.53,7253.67 C10.1@3469.96,7238.24 ; R28.2@3281.9,7311.35 3281.9,7304.85 3334.05,7252.7 R21.2@3375.35,7252.7 ; C10.1@3469.2,7238.73 C10.1@3470.01,7237.92
NetC11_1: C11.1 R31.2 R34.1 U1.8 | length 287.2
  Top Layer w8: R34.1@2476.83,7269.1 2486.84,7279.11 C11.1@2549.85,7279.11 R31.2@2617.96,7279.11 2617.96,7270.28 2679.72,7270.28 2704.48,7245.52 U1.8@2704.48,7209.19
NetC11_2: C11.2 R29.1 R31.1 U1.9 | length 283.8
  Top Layer w8: R29.1@2476.83,7177.29 2512,7177.29 2549.85,7215.14 C11.2@2549.85,7216.12 R31.1@2617.96,7216.12 2617.96,7189.04 2647.81,7159.19 U1.9@2704.48,7159.19
NetC12_1: C12.1 C13.1 R32.1 U5.10 U6.2 | length 32.5
  Top Layer w8: U6.2@906.97,6633.73 907.01,6633.78 v1(938.44,6633.83) v1(938.44,6633.83)
  Power w15: v1@938.02,6633.02 v1@938.02,6634.02
  other v1: 995.8,7200.49 966.09,7200.91 996.22,7232.29 965.25,7232.71
NetC15_1: C15.1 R29.2 R34.2 TP7.1 U4.7 | length 1106
  Top Layer w8: U4.7@1783.7,7131.57 1722.98,7131.57 1705.28,7149.26 1705.28,7191.8 1734.2,7220.73 2275.3,7220.73 TP7.1@2318.74,7177.29 R29.2@2396.83,7177.29 ; v1(2396.83,7109.19) R29.2@2396.83,7177.29 ; R34.2@2396.83,7269.1 R29.2@2396.83,7177.29
  Bottom Layer w8: v1(2396.83,7109.19) 2399.12,7111.49 2403.26,7111.49 2461.52,7169.74 C15.1@2468.02,7169.74
NetC16_1: C16.1 R38.2 R43.1 U1.14 | length 287.6
  Top Layer w8: C16.1@2526.78,6866.85 2537.58,6856.05 2590.14,6856.05 R38.2@2602.64,6868.55 ; R43.1@2601.32,6781.52 2602.64,6782.83 R38.2@2602.64,6858.55 2602.64,6861.5 2650.33,6909.19 U1.14@2704.48,6909.19
NetC16_2: C16.2 R36.1 R38.1 U1.13 | length 308.1
  Top Layer w8: R36.1@2433.3,6931.58 2443.34,6921.54 2592.64,6921.54 2602.64,6931.54 2602.64,6932.52 2613.62,6921.54 2613.62,6934.38 2638.43,6959.19 U1.13@2704.48,6959.19
NetC19_1: C19.1 R36.2 R43.2 TP11.1 U4.8 | length 1105.1
  Top Layer w8: U4.8@1783.7,7181.57 2179.18,7181.57 2252.76,7107.98 TP11.1@2252.76,6850.1 2335.72,6850.1 2344.99,6840.83 2422.56,6840.83 2433.3,6851.58 R36.2@2433.3,6841.58 2433.3,6797.17 2460.97,6769.51 2509.32,6769.51 R43.2@2521.32,6781.52
NetC20_1: C20.1 J6.11 R46.1 S1.2 U6.23 | length 1102.4
  Top Layer w8: J6.11@150,6571.53 151.15,6571.53 196.26,6616.64 196.26,6692.82 227.23,6723.8 298.99,6723.8 484.97,6909.79 v1(670.55,6909.79) 684.53,6895.81 U6.23@684.53,6856.18
  Bottom Layer w8: v1(670.55,6909.79) 670.55,6952.43 684.53,6966.41 R46.1@681.05,6969.88 ; C20.1@765.65,6965.41 C20.1@765.65,6971.91
  Bottom Layer w10: S1.2@593.82,7076.46 654.78,7076.46 681.05,7050.18 R46.1@681.05,6969.88 763.62,6969.88 C20.1@765.65,6971.91
NetC21_1: C21.1 R49.2 R52.1 U2.14 | length 288.9
  Top Layer w8: R52.1@2108,6160 2112,6164 2167.27,6164 2203.54,6200.27 C21.1@2203.54,6201.26 ; C21.1@2203,6203 2205.76,6200.24 R49.2@2273.99,6200.24 ; R49.2@2276,6200 2277,6201 2315,6201 2324.02,6210.02 2371.95,6210.02 U2.14@2374.37,6212.45
NetC21_2: C21.2 R47.1 R49.1 U2.13 | length 268.3
  Top Layer w8: R47.1@2113,6266 2114.75,6264.25 C21.2@2203.54,6264.25 ; C21.2@2202,6262 2203.23,6263.23 R49.1@2273.99,6263.23 ; R49.1@2270,6262 2373.92,6262 U2.13@2374.37,6262.45
NetC22_1: C22.1 R47.2 R52.2 TP15.1 U4.9 | length 1556.1
  Top Layer w8: v1(1315,7181.57) U4.9@1413.62,7181.57 ; v1(1974.63,6345.88) 2030.17,6345.88 2033.79,6345.88 C22.1@2037.84,6345.88 ; TP15.1@2030.13,6073.66 2030.13,6160.3 R52.2@2033.49,6163.66 2033.49,6264.49 R47.2@2034.7,6265.7 ; C22.1@2031.08,6341.92 2034.7,6338.3 R47.2@2034.7,6265.7 ; R47.2@2034.7,6262.41 R47.2@2034.7,6265.7 ; R47.2@2039,6270 R47.2@2034.7,6265.7
  Signal w6.5: v1(1315,7181.57) 1950.29,6546.27 1950.29,6367.17 v1@1975.54,6341.92
NetC23_1: C23.1 U6.45 Y1.2 | length 167.6
  Top Layer w8: C23.1@772.37,6456.19 772.37,6497.17 789.94,6514.73 814.79,6514.73 816.81,6516.75 816.81,6546.17 822.32,6551.68 U6.45@822.32,6588.46
NetC25_1: C25.1 R55.2 R57.1 U2.7 | length 271
  Top Layer w8: U2.7@2775.45,6512.45 2828.7,6512.45 2843,6526.74 R55.2@2883.08,6526.74 ; R57.1@2886,6612 2886,6529.67 R55.2@2883.08,6526.74 ; C25.1@2954.06,6526.74 R55.2@2883.08,6526.74
NetC25_2: C25.2 R54.1 R55.1 U2.6 | length 310.8
  Top Layer w8: U2.6@2775.45,6462.45 2881.77,6462.45 R55.1@2883.08,6463.75 C25.2@2954.06,6463.75 2997.11,6463.75 3013.76,6447.1 R54.1@3078.79,6447.1
NetC26_1: C26.1 U6.46 Y1.1 | length 174.3
  Top Layer w8: U6.46@842.01,6588.46 842.01,6553.25 850.66,6544.6 850.66,6519.61 Y1.1@852.22,6518.05 852.22,6515.4 883.62,6515.4 897.87,6501.14 C26.1@897.87,6455.71
NetC27_1: C27.1 R54.2 R57.2 TP18.1 U4.10 | length 2149.5
  Top Layer w8: U4.10@1413.62,7131.57 1509.43,7131.57 1657,6984 1657,6817.28 1729.28,6745 2132.2,6745 2189.2,6688 TP18.1@3046.16,6688 ; R57.2@2966,6612 3045.3,6612 TP18.1@3045.3,6675.44 ; C27.1@3046.16,6606.37 3078.79,6573.74 R54.2@3078.79,6527.1
NetC28_1: C28.1 R58.1 U7.3 | length 365.9
  Top Layer w8: C28.1@3359.46,6572.87 3452.45,6572.87 R58.1@3452.82,6573.23 3452.82,6420.74 3481,6392.56 U7.3@3561.06,6392.56
NetC28_2: C28.2 TP17.1 U2.5 U7.5 | length 814.2
  Top Layer w8: U2.5@2775.45,6412.45 2836.22,6412.45 v1(2852.91,6429.14) ; v1(3276.73,6442.56) U7.5@3190.98,6442.56 3186.4,6447.13 3186.4,6554.88 3204.39,6572.87 C28.2@3279.46,6572.87
  Bottom Layer w8: v1(2852.91,6429.14) 2866.33,6442.56 v1(3276.73,6442.56)
NetC29_1: C29.1 R58.2 U7.4 | length 249.9
  Top Layer w8: R58.2@3520.93,6573.23 3520.93,6526.07 3557,6490 v1(3557,6484) 3557,6450.5 3563,6444.5 U7.4@3561.06,6442.56
  Bottom Layer w10: C29.1@3528.69,6573.23 3528.69,6512.31 v1(3557,6484)
NetC30_1: C30.1 R64.2 R68.1 U2.8 | length 353.4
  Top Layer w8: R68.1@2100,6620 2108.59,6620 2157.37,6571.22 C30.1@2202.57,6571.22 C30.1@2202.57,6562.22 ; C30.1@2205,6560 2207.22,6562.22 R64.2@2271.46,6562.22 ; R64.2@2266,6560 R64.2@2272.69,6560 ; R64.2@2271.46,6571.22 2350.21,6571.22 2374.37,6547.06 U2.8@2374.37,6512.45
NetC30_2: C30.2 R59.1 R64.1 U2.9 | length 288.1
  Top Layer w8: R59.1@2113,6511 2120,6504 C30.2@2197.8,6504 ; C30.2@2201,6502 2203.77,6499.23 R64.1@2271.46,6499.23 ; R64.1@2271.46,6508.23 2271.46,6507.24 2316.26,6462.45 U2.9@2374.37,6462.45 ; R64.1@2274,6495.7 R64.1@2274,6502
NetC31_1: C31.1 Q1.2 R66.1 | length 311.5
  Top Layer w8: R66.1@2061.46,7494.42 2062.07,7493.81 C31.1@2181.05,7493.81 2182.01,7492.85 Q1.2@2372.27,7492.85
NetC31_2: C31.2 Q1.1 Q1.3 R69.1 | length 337.5
  Top Layer w8: R69.1@2063.97,7408.63 2177.76,7408.63 C31.2@2182.14,7413.01 ; C31.2@2187.55,7413.81 2229.2,7455.45 Q1.3@2277.78,7455.45 2285.66,7455.45 2323.06,7418.05 2371.12,7418.05 Q1.1@2371.98,7418.91
NetC32_1: C32.1 R59.2 R68.2 TP21.1 U4.11 | length 1162.1
  Top Layer w8: U4.11@1413.62,7081.57 1501.12,7081.57 1610,6972.69 1610,6811.19 1697.22,6723.96 2003.45,6723.96 2032,6695.42 R68.2@2032,6621.51 R68.2@2032,6612.51 ; v1(1980,6612) 2031.49,6612 R68.2@2032,6612.51 ; R59.2@2032,6512.45 R59.2@2032,6521.45 R68.2@2032,6612.51
  Bottom Layer w8: v1(1980,6612) C32.1@2034,6612
NetC36_2: C36.2 R77.2 R82.2 TP22.1 U9.3 | length 786.5
  Top Layer w8: v1@2785.48,5158.57 2854.68,5158.57 2904.44,5158.53 2917.8,5171.89 C36.2@2978.54,5171.89 2978.54,5101.04 2973.17,5095.68 2978.54,5090.32 TP22.1@2978.54,4971.35
  Bottom Layer w8: R82.2@2764.02,5532.55 2764.02,5180.02 v1(2785.44,5158.6)
NetC37_1: C37.1 R75.2 R76.1 | length 209.7
  Top Layer w8: R76.1@3226.52,5091.09 3226.52,5097.59 3258.17,5129.24 3258.17,5167.17 C37.1@3254.5,5170.84 ; C37.1@3253.48,5171.86 C37.1@3254.5,5170.84 ; R75.2@3368.41,5170.84 C37.1@3254.5,5170.84
NetC38_1: C38.1 R76.2 R77.1 | length 194.9
  Top Layer w8: R77.1@3047.98,5090.49 R76.2@3133.85,5090.49 ; C38.1@3115.56,5183.04 3115.56,5128.56 3146.52,5097.59 R76.2@3146.52,5091.09 R76.2@3143.52,5094.1
NetC42_1: C42.1 R109.1 R110.1 TP27.1 U14.10
NetC44_1: C44.1 C45.1 C46.1 C47.1 C48.1 J16.2 R111.2 TP28.1 U13.6 U13.7 U13.8
NetC44_2: C44.2 D6.2 R112.1 R116.2 U13.9 | length 510.7
  Top Layer w10: U13.9@1029.99,4916.92 1047.12,4916.92 1070.11,4939.91 C44.2@1135.84,4939.91 1135.84,5014.08 1126.04,5023.87 v1(1055.93,5023.87)
  Bottom Layer w10: v1(1055.93,5023.87) 1101.68,5023.87 1116.21,5038.4 D6.2@1116.21,5094.62 1227.84,5094.62 R116.2@1230.01,5092.46
NetC45_2: C45.2 C48.2 R114.1 R115.1
NetC51_1: C51.1 C52.1 C53.1 C54.1 C55.1 J18.2 R117.2 TP31.1 U15.6 U15.7 U15.8
NetC51_2: C51.2 D9.2 R118.1 R123.2 U15.9 | length 497.1
  Top Layer w10: U15.9@1030.71,5440.09 1047.84,5440.09 1068.81,5461.06 1125.81,5461.06 C51.2@1127.05,5459.82 ; v1(1056.65,5546.51) R118.1@1127.05,5546.51 C51.2@1127.05,5459.82 ; C51.2@1127.82,5459.05 C51.2@1127.05,5459.82
  Bottom Layer w10: v1(1056.65,5546.51) 1094.97,5546.51 1116.93,5568.46 D9.2@1116.93,5617.78 1228.56,5617.78 R123.2@1230.72,5615.62
NetC54_2: C54.2 C55.2 R120.1 R122.1
NetC56_1: C56.1 C57.1 D8.1 J19.3 TP33.1 U15.2 U15.3 U15.4
NetC60_2: C60.2 Q4.1 R124.1 R126.2 | length 561.4
  Top Layer w12: Q4.1@1819.44,5820.97 1818.91,5821.5 1818.91,5846.9 1835.14,5863.13 1937.95,5863.13 1960.29,5840.79 v1(1960.29,5758.41) 1960.29,5720.12 1942.83,5702.65 R126.2@1884.59,5702.65
  Bottom Layer w12: R124.1@1880,5764 1886.4,5757.6 1959.48,5757.6 v1(1960.29,5758.41) ; R124.1@1884.04,5763 C60.2@1884.04,5854
NetC61_2: C61.2 U32.12 | length 111.2
  Top Layer w12: U32.12@1042.12,4370.75 1045.87,4374.5 v1(1091.25,4374.5)
  Bottom Layer w12: v1(1091.25,4374.5) 1136.59,4374.5 C61.2@1147.32,4385.23
NetC62_1: C62.1 Q9.1 R132.1 R133.2 | length 381
  Top Layer w12: R132.1@1803.72,5351.59 1819.44,5335.86 Q9.1@1819.44,5256 1846,5256 1880.09,5290.09 v1(1940,5290.09)
  Bottom Layer w12: C62.1@1884.04,5207.77 R133.2@1884.04,5294.26 1888.22,5290.09 v1(1940,5290.09)
NetC63_1: C63.1 C64.1 C65.1 C66.1 C67.1 J20.2 R134.2 TP35.1 U16.6 U16.7 U16.8
NetC63_2: C63.2 D11.2 R135.1 R139.2 U16.9 | length 498.8
  Top Layer w10: U16.9@2104.84,4384.68 2121.96,4384.68 2138.34,4401.05 2187.95,4401.05 C63.2@2194,4395 R135.1@2194,4484.91 ; v1(2124.09,4500.83) 2141.45,4483.48 2192.56,4483.48 R135.1@2194,4484.91 ; R135.1@2195,4485.91 R135.1@2194,4484.91
  Bottom Layer w10: v1(2124.09,4500.83) 2170.79,4500.83 2191.06,4521.1 D11.2@2191.06,4562.38 2302.69,4562.38 R139.2@2304.85,4560.22
NetC66_2: C66.2 C67.2 R137.1 R138.1
NetC70_1: C70.1 R141.1 R146.1 U17.1 | length 347.6
  Top Layer w8: v1@3036.7,2959.19 v1(3037,2959.19) U17.1@3105.56,2959.19 3197.39,2959.19 3211.85,2944.73 3211.85,2856.31 R141.1@3204.54,2849
  Bottom Layer w8: R146.1@2973.08,2950.1 2982.17,2959.19 v1(3037,2959.19)
NetC70_2: C70.2 J21.2 R140.1 R145.1 TP37.1 U17.2 | length 822.7
  Top Layer w8: v1(3037,3010) 3104.75,3010 U17.2@3105.56,3009.19 3205.28,3009.19 3209.42,3013.33 R140.1@3304.76,3013.33 3305.09,3013 TP37.1@3474,3013 3489.75,3013 3549.85,3073.1 J21.2@3735,3073.1
  Bottom Layer w8: v1(3037,3010) 3039.3,3007.7 3039.3,2993.88 3090.55,2942.63 R145.1@3098.62,2942.63
NetC71_1: C71.1 R146.2 TP38.1 U20.1 | length 3287.1
  Top Layer w6: TP38.1@2904,3353.48 2915,3342.48 v1(2915,3259)
  Top Layer w8: U20.1@906.97,2664.05 936.7,2664.05 936.92,2663.83 1030.21,2663.83 v1(1031.73,2665.34)
  Signal w6.5: v1(1031.73,2665.34) 965.33,2731.74 965.33,2754.33 983.26,2772.27 1976.82,2772.27 2175.01,2574.08 2855.57,2574.08 2914.94,2633.45 v1@2914.94,3259.08
  Bottom Layer w8: v1(2915,3259) 2915,3172.51 2965.42,3122.09 C71.1@2971.92,3122.09 2971.92,3031.26 R146.2@2973.08,3030.1
NetC73_1: C73.1 R154.2 TP39.1 U20.4 | length 2168.6
  Top Layer w8: U20.4@906.97,2723.11 963.22,2723.11 973.81,2712.52 v1(1022.97,2712.52) ; TP39.1@2646.5,2122.08 2647,2122.58 v1(2647,2176.94)
  Signal w6.5: v1@1022.91,2712.6 1902.69,2712.6 2438.34,2176.94 v1(2647,2176.94)
  Bottom Layer w8: C73.1@2566.57,2221.9 C73.1@2564,2224.47 2637.81,2224.47 R154.2@2647,2233.66 v1(2647,2176.94)
NetC74_1: C74.1 R163.2 TP41.1 U20.5 | length 3408.2
  Top Layer w8: U20.5@906.97,2742.79 v1(989.43,2742.76) ; R163.2@3280.71,3276.27 3367.1,3276.27 C74.1@3374.38,3283.55 3374.56,3283.73 TP41.1@3374.56,3385.55
  Signal w6.5: v1(989.43,2742.76) 1942.63,2742.84 2148.4,2537.08 2882.76,2537.08 2953.97,2608.29 2953.97,3165.27 3123.45,3334.75 v1(3374.47,3334.75)
NetC78_1: C78.1 R167.2 TP42.1 U20.6 | length 2031.7
  Top Layer w8: U20.6@906.97,2762.48 976.23,2762.48 990.58,2776.82 1769.82,2776.82 2333.3,3340.3 2502.7,3340.3 C78.1@2504,3339 ; TP42.1@2504.2,3440.36 2504.2,3339.2 C78.1@2504,3339 ; R167.2@2596.66,3340.69 2594.97,3339 C78.1@2504,3339
NetC81_1: C81.1 R176.2 TP46.1 U20.7 | length 1945.3
  Top Layer w6: v1(2499.82,2704.47) TP46.1@2499.82,2750.47
  Top Layer w8: U20.7@906.97,2782.16 964.81,2782.16 v1(981.42,2798.77) ; C81.1@2498.19,2863.92 C81.1@2499.82,2865.55 ; TP46.1@2499.82,2750.47 C81.1@2499.82,2865.55 ; C81.1@2499.82,2868.54 C81.1@2499.82,2865.55 ; R176.2@2592,2868 2503.35,2868 C81.1@2502.81,2868.54 C81.1@2499.82,2865.55
  Signal w6.5: v1(981.42,2798.77) 2001.87,2798.77 2151.58,2649.05 2446.25,2649.05 v1@2500.75,2703.55
NetC83_1: C83.1 J27.11 R179.1 S2.2 U20.23 | length 1099.9
  Top Layer w8: J27.11@150,2620.53 151.15,2620.53 197.37,2666.75 197.37,2749.12 220.39,2772.14 291.88,2772.14 479.52,2959.79 670.26,2959.79 v1(671.48,2958.57) 684.53,2945.52 U20.23@684.53,2906.18
  Bottom Layer w8: R179.1@684.53,3017.52 686.88,3019.88 R179.1@687,3020 ; C83.1@765.65,3015.41 C83.1@765.65,3021.91
  Bottom Layer w10: S2.2@593.82,3126.46 654.78,3126.46 681.05,3100.18 R179.1@681.05,3020.95 ; v1(671.48,2958.57) 671.48,3004.48 R179.1@684.53,3017.52 ; R179.1@686.88,3019.88 763.62,3019.88 C83.1@765.65,3021.91
NetC84_1: C84.1 R183.2 TP50.1 U20.16 | length 1842.9
  Top Layer w8: U20.16@822.32,2906.18 822.32,2885.15 835.47,2872 v1(842.59,2872) ; TP50.1@2057,2226.28 2171.72,2226.28 C84.1@2180,2218 2274.06,2218 R183.2@2275.06,2219.01
  Signal w6.5: v1(842.59,2872) 842.59,2870.82 938.29,2775.13 938.29,2726.91 1028.19,2637.01 1708.02,2637.01 v1@2119.94,2225.08
  other v1: 2120,2225
NetC85_1: C85.1 U20.45 Y2.2 | length 167.6
  Top Layer w8: C85.1@772.37,2505.19 772.37,2546.17 789.94,2563.73 814.79,2563.73 816.81,2565.75 816.81,2595.17 822.32,2600.68 U20.45@822.32,2637.46
NetC86_1: C86.1 U20.46 Y2.1 | length 174.3
  Top Layer w8: U20.46@842.01,2637.46 842.01,2602.25 850.66,2593.6 850.66,2568.61 852.22,2567.05 852.22,2564.4 883.62,2564.4 897.87,2550.14 C86.1@897.87,2504.71
NetC88_1: C88.1 R186.2 TP52.1 U20.17 | length 2405.7
  Top Layer w6: v1(2887.51,2648.22) TP52.1@2887.51,2703
  Top Layer w8: U20.17@802.64,2906.18 802.64,2924.16 v1(814.79,2936.32) ; v1(2887.51,2648.22) 2887.51,2603.94 R186.2@2900.17,2591.28
  Signal w6.5: v1@814.74,2936.4 2599.36,2936.4 v1@2887.45,2648.3
  Bottom Layer w8: v1(2887.51,2648.22) 2887.51,2604.67 C88.1@2900.17,2592.01
NetC89_1: C89.1 R187.1 U22.3 | length 362.4
  Top Layer w8: C89.1@3355.91,2606.93 R187.1@3440.54,2606.93 3440.54,2459.83 3473.74,2426.63 U22.3@3557.51,2426.63
NetC89_2: C89.2 TP53.1 U18.5 U22.5 | length 615.5
  Top Layer w8: U18.5@2775.84,2462.5 3008.1,2462.5 TP53.1@3017,2471.4 3022.23,2476.63 U22.5@3187.43,2476.63 3187.43,2571.02 3223.71,2607.3 3275.55,2607.3 C89.2@3275.91,2606.93
NetC90_1: C90.1 R187.2 U22.4 | length 239.1
  Top Layer w8: R187.2@3508.65,2606.93 3508.65,2598.86 3556,2551.51 3556,2533.51 v1(3557.51,2532) U22.4@3557.51,2476.63
  Bottom Layer w8: C90.1@3520,2605 3520,2598.5 3557.51,2560.99 v1(3557.51,2532)
NetC91_1: C91.1 Q10.2 R191.1 | length 323.3
  Top Layer w8: R191.1@2052.82,3549.37 2060.55,3541.65 Q10.2@2372.89,3541.65
NetC91_2: C91.2 Q10.1 Q10.3 R193.1 | length 362.4
  Top Layer w8: R193.1@2051.5,3464.66 2179.61,3464.66 2181.68,3462.6 C91.2@2182.88,3463.81 ; C91.2@2181.05,3463.81 C91.2@2182.88,3463.81 ; C91.2@2185.92,3466.84 C91.2@2182.88,3463.81 ; Q10.3@2277.21,3505.98 2276.98,3505.76 2229.5,3505.76 2187.55,3463.81 C91.2@2182.88,3463.81 ; Q10.3@2277.78,3505.45 2285.66,3505.45 2323.06,3468.05 Q10.1@2372.27,3468.05 Q10.1@2374,3468.05
NetC93_1: C93.1 R196.2 TP56.1 U20.18 | length 1753.4
  Top Layer w8: U20.18@782.95,2906.18 v1(782.95,2951.26) ; TP56.1@2167.62,2747 v1(2167.62,2693) 2167.62,2635.59 C93.1@2166.47,2634.44 2260.86,2634.44 R196.2@2261,2634.58
  Signal w6.5: v1@782.89,2951.35 782.89,2935.87 820.95,2897.81 1962.83,2897.81 v1@2167.56,2693.08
